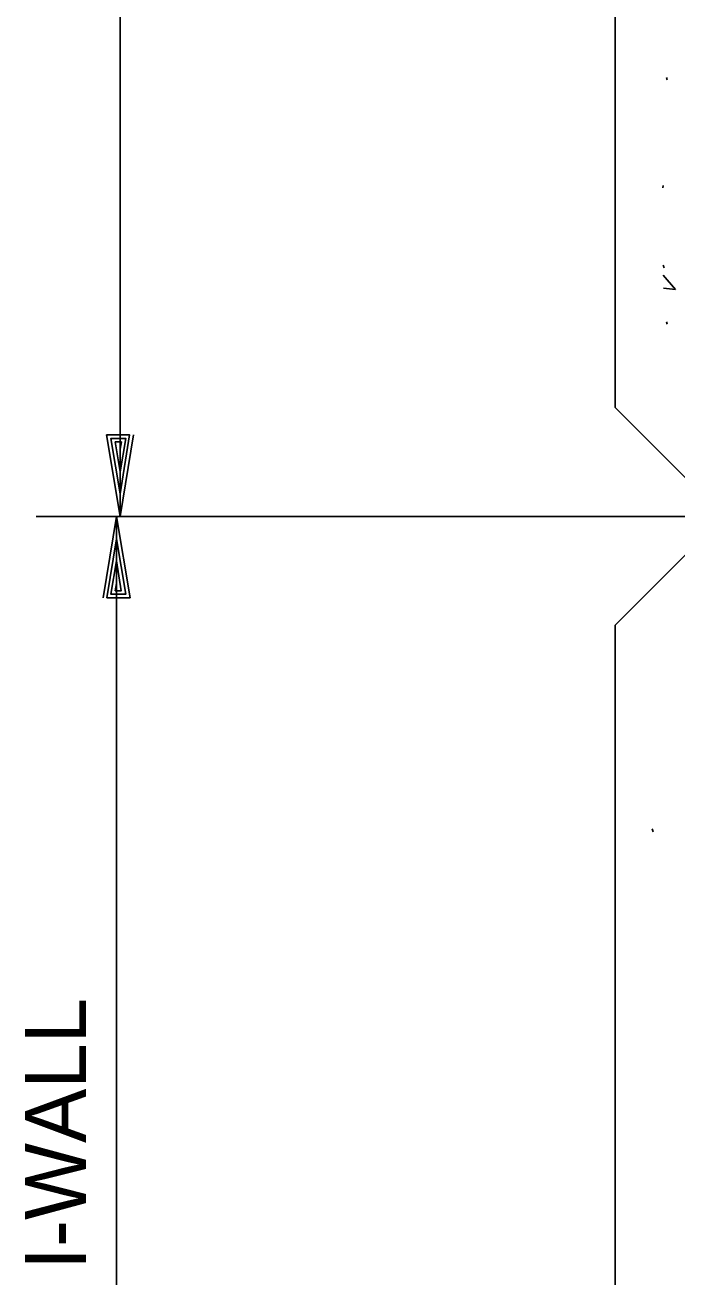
# Model space of a CAD drawing. Extents: x 44743.44 to 44747.1, y 44738.46 to 44741.29.
# Drawn here: x 44745.0546 to 44745.1793, y 44739.2099 to 44739.4495 of the extents above; entities that cross this region are included whole.
import ezdxf

# ---------------------------------------------------------------- set-up
doc = ezdxf.new("R2010")
doc.units = 0
for name, color, linetype in [('Level 1', 7, 'Continuous'), ('Level 10', 7, 'Continuous'), ('Level 8', 7, 'Continuous'), ('S-ANNO-TEXT', 7, 'Continuous')]:
    doc.layers.add(name, color=color, linetype=linetype)

msp = doc.modelspace()

# ---------------------------------------------------------------- linework, layer by layer
at = {"layer": 'Level 1'}
for p, q in [((44745.07273, 44739.60507), (44745.07273, 44739.35544)), ((44745.07273, 44739.35978), (44745.07273, 44739.35978)), ((44745.05668, 44739.35544), (44745.40747, 44739.35544)), ((44745.07206, 44739.10476), (44745.07206, 44739.35544)), ((44745.07206, 44739.35544), (44745.07206, 44739.35544)), ((44745.07273, 44739.35544), (44745.07273, 44739.35544)), ((44745.07206, 44739.35111), (44745.07206, 44739.35111))]:
    msp.add_line(p, q, dxfattribs=at)
for points in [[(44745.07532, 44739.37103), (44745.07273, 44739.35544), (44745.07015, 44739.37103), (44745.07457, 44739.37103), (44745.07273, 44739.35978), (44745.07098, 44739.37036), (44745.07382, 44739.37036), (44745.07273, 44739.36394), (44745.07182, 44739.36969), (44745.07298, 44739.36969), (44745.07273, 44739.36828)], [(44745.06947, 44739.33986), (44745.07206, 44739.35544), (44745.07464, 44739.33986), (44745.07022, 44739.33986), (44745.07206, 44739.35111), (44745.07381, 44739.34053), (44745.07097, 44739.34053), (44745.07206, 44739.34694), (44745.07297, 44739.34119), (44745.07181, 44739.34119), (44745.07206, 44739.34261)]]:
    msp.add_lwpolyline(points, dxfattribs=at)
at = {"layer": 'Level 10'}
for p, q in [((44745.16748, 44739.37627), (44745.16748, 44739.60507)), ((44745.16748, 44739.37627), (44745.1831, 44739.36064)), ((44745.16748, 44739.33461), (44745.1831, 44739.35023)), ((44745.16748, 44739.10476), (44745.16748, 44739.33461))]:
    msp.add_line(p, q, dxfattribs=at)
at = {"layer": 'Level 8'}
for p, q in [((44745.17742, 44739.43896), (44745.17724, 44739.43941)), ((44745.17742, 44739.3922), (44745.17724, 44739.39265))]:
    msp.add_line(p, q, dxfattribs=at)
for points in [[(44745.1766, 44739.41834), (44745.17666, 44739.41875)], [(44745.1768, 44739.40298), (44745.17666, 44739.40351)], [(44745.179, 44739.39888), (44745.17666, 44739.40159)], [(44745.17667, 44739.39914), (44745.179, 44739.39888)], [(44745.17475, 44739.29506), (44745.17454, 44739.29562)]]:
    msp.add_lwpolyline(points, dxfattribs=at)

# ---------------------------------------------------------------- texts
at = {"layer": 'S-ANNO-TEXT'}
msp.add_text('I-WALL', height=0.011667, rotation=90, dxfattribs=at).set_placement((44745.06622, 44739.21125))

doc.saveas('drawing.dxf')
